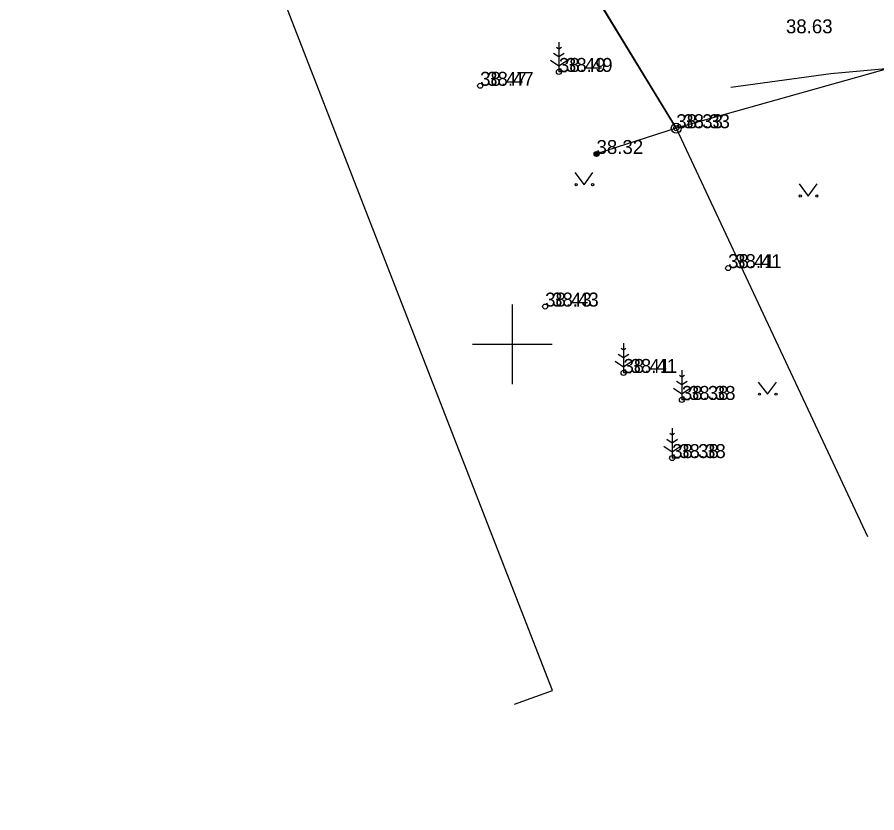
# Model space of a CAD drawing. Extents: x 627548 to 628052, y 6467984 to 6468802.
# Drawn here: x 627775.14 to 627818.31, y 6468376.46 to 6468416.43 of the extents above; entities that cross this region are included whole.
import ezdxf

# ---------------------------------------------------------------- set-up
doc = ezdxf.new("R2010")
doc.units = 0
for name, color, linetype in [('HALJASTUS', 7, 'Continuous'), ('KORGUS-EH2000', 7, 'Continuous'), ('MOOTKORG-EH2000', 7, 'Continuous'), ('MOOTMPUNKT', 7, 'Continuous'), ('MPOHULIIN', 7, 'Continuous'), ('PIIR', 7, 'Continuous'), ('POST', 7, 'Continuous'), ('PUU', 7, 'Continuous'), ('SIOHULIIN', 7, 'Continuous'), ('SITRASS', 7, 'Continuous'), ('VORK', 7, 'Continuous')]:
    doc.layers.add(name, color=color, linetype=linetype)

msp = doc.modelspace()

# ---------------------------------------------------------------- linework, layer by layer
at = {"layer": 'HALJASTUS'}
for p, q in [((627803.147, 6468408.621), (627803.611, 6468408.015)), ((627803.611, 6468408.015), (627804.056, 6468408.621)), ((627814.407, 6468408.052), (627814.87, 6468407.446)), ((627814.87, 6468407.446), (627815.316, 6468408.052)), ((627812.36, 6468398.095), (627812.823, 6468397.488)), ((627812.823, 6468397.488), (627813.269, 6468398.095))]:
    msp.add_line(p, q, dxfattribs=at)
for centre in [(627803.21, 6468408.015), (627804.038, 6468408.015), (627814.469, 6468407.446), (627815.298, 6468407.446), (627812.422, 6468397.488), (627813.251, 6468397.488)]:
    msp.add_circle(centre, 0.055, dxfattribs=at)
at = {"layer": 'MOOTMPUNKT'}
for centre in [(627802.347, 6468413.681), (627798.388, 6468412.985), (627808.24, 6468410.853), (627804.235, 6468409.558), (627810.843, 6468403.824), (627801.652, 6468401.893), (627805.59, 6468398.558), (627808.522, 6468397.202), (627808.033, 6468394.281)]:
    msp.add_circle(centre, 0.125, dxfattribs=at)
at = {"layer": 'MPOHULIIN'}
for p, q in [((627808.24, 6468410.853), (627776.772, 6468462.547)), ((627823.391, 6468415.126), (627808.24, 6468410.853))]:
    msp.add_line(p, q, dxfattribs=at)
at = {"layer": 'PIIR'}
for p, q in [((627802.03, 6468382.61), (627775.14, 6468451.7)), ((627800.122, 6468381.921), (627802.03, 6468382.61))]:
    msp.add_line(p, q, dxfattribs=at)
at = {"layer": 'POST'}
msp.add_lwpolyline([(627808.24, 6468410.853), (627804.235, 6468409.558)], dxfattribs=at)
for centre, radius in [((627808.24, 6468410.853), 0.25), ((627804.235, 6468409.558), 0.125), ((627804.235, 6468409.558), 0.117), ((627804.235, 6468409.558), 0.109), ((627804.235, 6468409.558), 0.102), ((627804.235, 6468409.558), 0.0938), ((627804.235, 6468409.558), 0.086), ((627804.235, 6468409.558), 0.0782), ((627804.235, 6468409.558), 0.0704), ((627804.235, 6468409.558), 0.0626), ((627804.235, 6468409.558), 0.0548), ((627804.235, 6468409.558), 0.047), ((627804.235, 6468409.558), 0.0392), ((627804.235, 6468409.558), 0.0314), ((627804.235, 6468409.558), 0.0236), ((627804.235, 6468409.558), 0.0158), ((627804.235, 6468409.558), 0.00798), ((627804.235, 6468409.558), 0.000186)]:
    msp.add_circle(centre, radius, dxfattribs=at)
at = {"layer": 'PUU'}
for p, q in [((627802.347, 6468415.181), (627802.347, 6468413.681)), ((627802.347, 6468414.431), (627802.08, 6468414.609)), ((627802.347, 6468414.831), (627802.223, 6468414.914)), ((627802.471, 6468414.914), (627802.347, 6468414.831)), ((627802.614, 6468414.609), (627802.347, 6468414.431)), ((627801.923, 6468414.27), (627802.347, 6468413.988)), ((627802.347, 6468413.988), (627802.771, 6468414.27)), ((627802.707, 6468413.681), (627802.347, 6468413.681)), ((627805.59, 6468400.058), (627805.59, 6468398.558)), ((627805.59, 6468399.308), (627805.323, 6468399.486)), ((627805.59, 6468399.708), (627805.466, 6468399.791)), ((627805.714, 6468399.791), (627805.59, 6468399.708)), ((627805.857, 6468399.486), (627805.59, 6468399.308)), ((627805.166, 6468399.147), (627805.59, 6468398.865)), ((627805.59, 6468398.865), (627806.014, 6468399.147)), ((627805.95, 6468398.558), (627805.59, 6468398.558)), ((627808.522, 6468398.702), (627808.522, 6468397.202)), ((627808.522, 6468397.952), (627808.255, 6468398.13)), ((627808.522, 6468398.352), (627808.398, 6468398.435)), ((627808.646, 6468398.435), (627808.522, 6468398.352)), ((627808.789, 6468398.13), (627808.522, 6468397.952)), ((627808.098, 6468397.791), (627808.522, 6468397.509)), ((627808.522, 6468397.509), (627808.946, 6468397.791)), ((627808.882, 6468397.202), (627808.522, 6468397.202)), ((627808.033, 6468395.431), (627807.909, 6468395.514)), ((627808.033, 6468395.781), (627808.033, 6468394.281)), ((627808.157, 6468395.514), (627808.033, 6468395.431)), ((627808.033, 6468395.031), (627807.766, 6468395.209)), ((627808.3, 6468395.209), (627808.033, 6468395.031)), ((627807.609, 6468394.87), (627808.033, 6468394.588)), ((627808.033, 6468394.588), (627808.457, 6468394.87)), ((627808.393, 6468394.281), (627808.033, 6468394.281))]:
    msp.add_line(p, q, dxfattribs=at)
at = {"layer": 'SIOHULIIN'}
for points in [[(627776.772, 6468462.547), (627808.24, 6468410.853)], [(627808.24, 6468410.853), (627817.841, 6468390.335)]]:
    msp.add_lwpolyline(points, dxfattribs=at)
at = {"layer": 'SITRASS'}
msp.add_lwpolyline([(627810.98, 6468412.92), (627816.008, 6468413.596), (627821.508, 6468414.106), (627822.696, 6468413.373), (627824.885, 6468409.551), (627827.286, 6468404.81), (627834.996, 6468390.373), (627839.865, 6468381.11), (627848.975, 6468360.983), (627852.832, 6468354.033), (627854.055, 6468352.951), (627855.398, 6468352.508), (627856.692, 6468352.349), (627857.78, 6468352.478), (627859.022, 6468352.51)], dxfattribs=at)
at = {"layer": 'VORK'}
for p, q in [((627800, 6468402), (627800, 6468398)), ((627798, 6468400), (627802, 6468400))]:
    msp.add_line(p, q, dxfattribs=at)

# ---------------------------------------------------------------- texts
at = {"layer": 'KORGUS-EH2000'}
for s, p in [(' 38.63', (627813.488, 6468415.621)), ('38.49', (627802.697, 6468413.681)), ('38.47', (627798.738, 6468412.985)), ('38.33', (627808.59, 6468410.853)), ('38.41', (627811.193, 6468403.824)), ('38.43', (627802.002, 6468401.893)), ('38.41', (627805.94, 6468398.558)), ('38.38', (627808.872, 6468397.202)), ('38.38', (627808.383, 6468394.281))]:
    msp.add_text(s, height=0.7, dxfattribs=at).set_placement(p)
at = {"layer": 'MOOTKORG-EH2000'}
for s, p in [('38.49', (627802.347, 6468413.681)), ('38.47', (627798.388, 6468412.985)), ('38.33', (627808.24, 6468410.853)), ('38.32', (627804.235, 6468409.558)), ('38.41', (627810.843, 6468403.824)), ('38.43', (627801.652, 6468401.893)), ('38.41', (627805.59, 6468398.558)), ('38.38', (627808.522, 6468397.202)), ('38.38', (627808.033, 6468394.281))]:
    msp.add_text(s, height=0.7, dxfattribs=at).set_placement(p)

doc.saveas('drawing.dxf')
